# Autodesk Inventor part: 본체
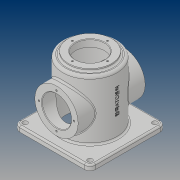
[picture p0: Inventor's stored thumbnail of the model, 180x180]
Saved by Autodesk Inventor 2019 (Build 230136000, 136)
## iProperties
Created: 2019-03
Part Number: 본체
Material: 일반
Document SubType Name: Modeling
Designer: PC312-09
Density: 1 g/cm^3
Appearance: 기본값
Author: PC312-09
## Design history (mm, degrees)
sketch "스케치1"
  geometry: C1 r 50 at (0, 0); 1 further point
  constraints: 1 centre point, 1 coincident
  dimensions: "d0" = 100 diameter of C1
extrude "돌출1" new body sketch "스케치1" distance "d1" = 120; taper "d2" = 0 deg
node "작업 평면1"
sketch "스케치6"
  geometry: C1 r 45 at (0, 0); 1 further point
  constraints: 1 centre point, 1 coincident
  dimensions: "d13" = 90 diameter of C1
extrude "돌출4" cut sketch "스케치6" distance "d14" = 112; taper "d15" = 0 deg
sketch "스케치7"
  geometry: L1 (-70, 70)-(70, 70); L2 (70, 70)-(70, -70); L3 (70, -70)-(-70, -70); L4 (-70, -70)-(-70, 70); L5 (-70, 70)-(70, -70); L6 (70, 70)-(-70, -70); C1 r 45 at (0, 0) reference; 1 further point
  constraints: 12 end point, 2 midpoint, 2 parallel, 1 horizontal, 1 perpendicular
  dimensions: "d16" = 140 distance of L1.start L1.end; "d17" = 140 distance of L1.end L2.end
extrude "돌출5" join sketch "스케치7" distance "d18" = 10; taper "d19" = 0 deg
node "작업 평면2"
sketch "스케치8"
  geometry: L1 (-70, 0)-(70, 0) reference; C1 r 40 at (0, 60); 2 further points
  constraints: 1 centre point, 1 midpoint, 1 vertical alignment
  dimensions: "d21" = 80 diameter of C1; "d22" = 60 distance from line of L1 C1.centre
extrude "돌출6" join sketch "스케치8" stored distance "d23" = 10; taper "d24" = 0 deg
sketch "스케치9"
  geometry: C1 r 40 at (0, 0) reference; C2 r 27 at (0, 0); 1 further point
  constraints: 1 centre point, 1 coincident
  dimensions: "d25" = 54 diameter of C2
extrude "돌출7" cut sketch "스케치9" distance "d26" = 50; taper "d27" = 0 deg
sketch "스케치10" dims "d28" = 65
  geometry: C1 r 27 at (0, 0) reference; 3 further points
  constraints: 2 vertical alignment, 1 coincident, 2 other
hole "구멍1" sketch "스케치10" at (0, 32.5) diameter "d29" = 3.242; stored, may be unused: countersink angle "d33" = 90 deg, drill point angle "d35" = 118 deg; dims "d30" = 8, "d31" = 4, "d32" = 2, "d34" = 10
sketch "스케치11"
  geometry: C1 r 50 at (0, 0) reference; C2 r 40 at (0, 0); 1 further point
  constraints: 1 centre point, 1 coincident
  dimensions: "d39" = 80 diameter of C2
extrude "돌출8" join sketch "스케치11" distance "d40" = 5; taper "d41" = 0 deg
sketch "스케치12"
  geometry: C1 r 40 at (0, 0) reference; C2 r 27 at (0, 0); 1 further point
  constraints: 1 centre point, 1 coincident
  dimensions: "d42" = 54 diameter of C2
extrude "돌출9" cut sketch "스케치12" distance "d43" = 50; taper "d44" = 0 deg
sketch "스케치13" dims "d45" = 65
  geometry: C1 r 50 at (0, 0) reference; 3 further points
  constraints: 2 vertical alignment, 1 coincident, 2 other
hole "구멍2" sketch "스케치13" at (0, 32.5) diameter "d46" = 3.242; stored, may be unused: countersink angle "d50" = 90 deg, drill point angle "d52" = 118 deg; dims "d47" = 8, "d48" = 4, "d49" = 2, "d51" = 10
fillet "모깎기1" dims "d56" = 10
sketch "스케치14"
  geometry: A1 r 10 centre (-60, -60) between (-70, -60) and (-60, -70) reference; A2 r 10 centre (60, -60) between (60, -70) and (70, -60) reference; A3 r 10 centre (60, 60) between (70, 60) and (60, 70) reference; A4 r 10 centre (-60, 60) between (-60, 70) and (-70, 60) reference; 5 further points
  constraints: 4 coincident
hole "구멍3" sketch "스케치14" at (-60, -60), (60, -60), (60, 60), (-60, 60) diameter "d57" = 9; stored, may be unused: countersink angle "d61" = 90 deg, drill point angle "d63" = 0 deg; dims "d58" = 8, "d59" = 4, "d60" = 2, "d62" = 10
fillet "모깎기2" dims "d64" = 3
fillet "모깎기3" dims "d65" = 3
chamfer "모따기1" distance "d67" = 1; stored, may be unused: second distance "d68" = 2, angle "d69" = 45 deg
fillet "모깎기5" dims "d70" = 3
node "작업 평면3"
sketch "스케치15"
  geometry: L1 (0, 60)-(0, -60) reference; 3 further points
  constraints: 1 horizontal alignment, 1 midpoint, 1 other
  dimensions: "d72" = 70 distance from line of L1 point (70, 0)
feature "엠보싱1" sketch "스케치15" dims "d1" = 120, "d2" = 0, "d73" = 0.5, "d74" = 0
fillet "모깎기6" dims "d78" = 5
fillet "모깎기7" dims "d79" = 3
node "솔리드1"
pattern_circular "원형 패턴1" dims angle "d37" = 360 deg
mirror "미러1"
pattern_circular "원형 패턴2" dims angle "d54" = 360 deg
other parameters: "d7" = 62, "d20" = 62, "d71" = 51.75
